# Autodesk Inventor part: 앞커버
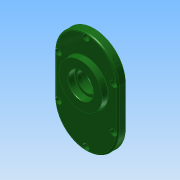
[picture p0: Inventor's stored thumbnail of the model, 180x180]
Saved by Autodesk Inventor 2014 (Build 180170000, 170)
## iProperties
Created: 2016-12
Part Number: 앞커버
Material: 알루미늄 6061
Document SubType Name: Modeling
Designer: mduedu
Density: 2.71 g/cm^3
Appearance: 매끄러움 - 짙은 산림 녹색
Mass: 264.671 g
Surface Area: 264.413 cm^2
Volume: 97.6646 cm^3
Author: mduedu
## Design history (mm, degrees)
sketch "스케치1"
  geometry: L1 (40, -25)-(40, 25); L2 (-40, 25)-(-40, -25); L3 (-40, -25)-(40, 25); L4 (40, -25)-(-40, 25); A1 r 40 centre (0, 25) between (40, 25) and (-40, 25); A2 r 40 centre (0, -25) between (-40, -25) and (40, -25); 1 further point
  constraints: 8 end point, 4 point on circle, 4 tangent, 2 centre point, 2 midpoint, 1 parallel, 1 vertical
  dimensions: "d0" = 130 dimension on A2 A1; "d2" = 80 distance between parallel lines of L1 L2
extrude "돌출1" new body sketch "스케치1" distance "d3" = 10; taper "d4" = 0 deg
sketch "스케치2"
  geometry: C1 r 21 at (0, 11); 1 further point
  constraints: 1 centre point, 1 vertical alignment
  dimensions: "d5" = 42 diameter of C1; "d7" = 11 distance of C1.centre point (0, 0)
extrude "돌출2" join sketch "스케치2" distance "d8" = 7; taper "d9" = 0 deg
sketch "스케치3"
  geometry: C1 r 15 at (0, -33.1); C2 r 21 at (0, 11) reference; 1 further point
  constraints: 1 centre point, 1 vertical alignment
  dimensions: "d10" = 30 diameter of C1; "d71" = 44.1 distance of C1.centre C2.centre
extrude "돌출3" join sketch "스케치3" distance "d12" = 7; taper "d13" = 0 deg
sketch "스케치4"
  geometry: C1 r 28 at (0, 11); A1 r 21 centre (0, 11) between (8.978, -7.984) and (-8.978, -7.984) reference; 1 further point
  constraints: 1 centre point, 1 coincident
  dimensions: "d14" = 56 diameter of C1
extrude "돌출4" join sketch "스케치4" distance "d15" = 7; taper "d16" = -5 deg
hole "구멍1" diameter "d19" = 35; stored, may be unused: countersink angle "d23" = 90 deg, drill point angle "d25" = 0 deg; dims "d17" = 10, "d18" = 10, "d20" = 6, "d21" = 4, "d22" = 2, "d24" = 10
hole "구멍2" diameter "d28" = 22; stored, may be unused: countersink angle "d32" = 90 deg, drill point angle "d34" = 0 deg; dims "d26" = 10, "d27" = 10, "d29" = 6, "d30" = 4, "d31" = 2, "d33" = 7
hole "구멍3" diameter "d37" = 19; stored, may be unused: countersink angle "d41" = 90 deg, drill point angle "d43" = 0 deg; dims "d35" = 10, "d36" = 10, "d38" = 6, "d39" = 4, "d40" = 2, "d42" = 1
hole "구멍4" diameter "d46" = 32; stored, may be unused: countersink angle "d50" = 90 deg, drill point angle "d52" = 0 deg; dims "d47" = 6, "d48" = 4, "d49" = 2, "d51" = 8.3, "d89" = 10, "d90" = 10
hole "구멍5" diameter "d55" = 25; stored, may be unused: countersink angle "d59" = 90 deg, drill point angle "d61" = 0 deg; dims "d53" = 10, "d54" = 10, "d56" = 6, "d57" = 4, "d58" = 2, "d60" = 8
fillet "모깎기1" dims "d62" = 0.3
fillet "모깎기2" dims "d63" = 2
chamfer "모따기1" distance "d64" = 1; stored, may be unused: second distance "d65" = 2, angle "d66" = 45 deg
chamfer "모따기2" distance "d91" = 0.8; stored, may be unused: second distance "d92" = 2, angle "d93" = 30 deg
fillet "모깎기4" dims "d68" = 2
fillet "모깎기5" dims "d69" = 0.3
fillet "모깎기6" dims "d70" = 2
sketch "스케치5"
  geometry: L1 (-40, 25)-(-40, -25) reference; L2 (40, -25)-(40, 25) reference; L3 (35, 25)-(35, -25); L4 (-35, -25)-(-35, 25); A1 r 40 centre (0, 25) between (40, 25) and (-40, 25) reference; A2 r 40 centre (0, -25) between (-40, -25) and (40, -25) reference; A3 r 35 centre (0, 25) between (35, 25) and (-35, 25); A4 r 35 centre (0, -25) between (-35, -25) and (35, -25); 2 further points
  constraints: 5 point on circle, 4 end point, 2 centre point, 1 vertical alignment, 3 other
  dimensions: "d72" = 5 distance between parallel lines of L2 L3
sketch "스케치7"
  geometry: 1 further point
  constraints: 1 other
hole "구멍7" sketch "스케치7" at (0, 60) diameter "d80" = 4.5; stored, may be unused: countersink angle "d84" = 90 deg, drill point angle "d86" = 0 deg; dims "d81" = 6, "d82" = 8, "d83" = 4.6, "d85" = 8
node "솔리드1"
pattern_linear "직사각형 패턴1"
